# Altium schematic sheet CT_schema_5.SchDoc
size 578 x 363 mm
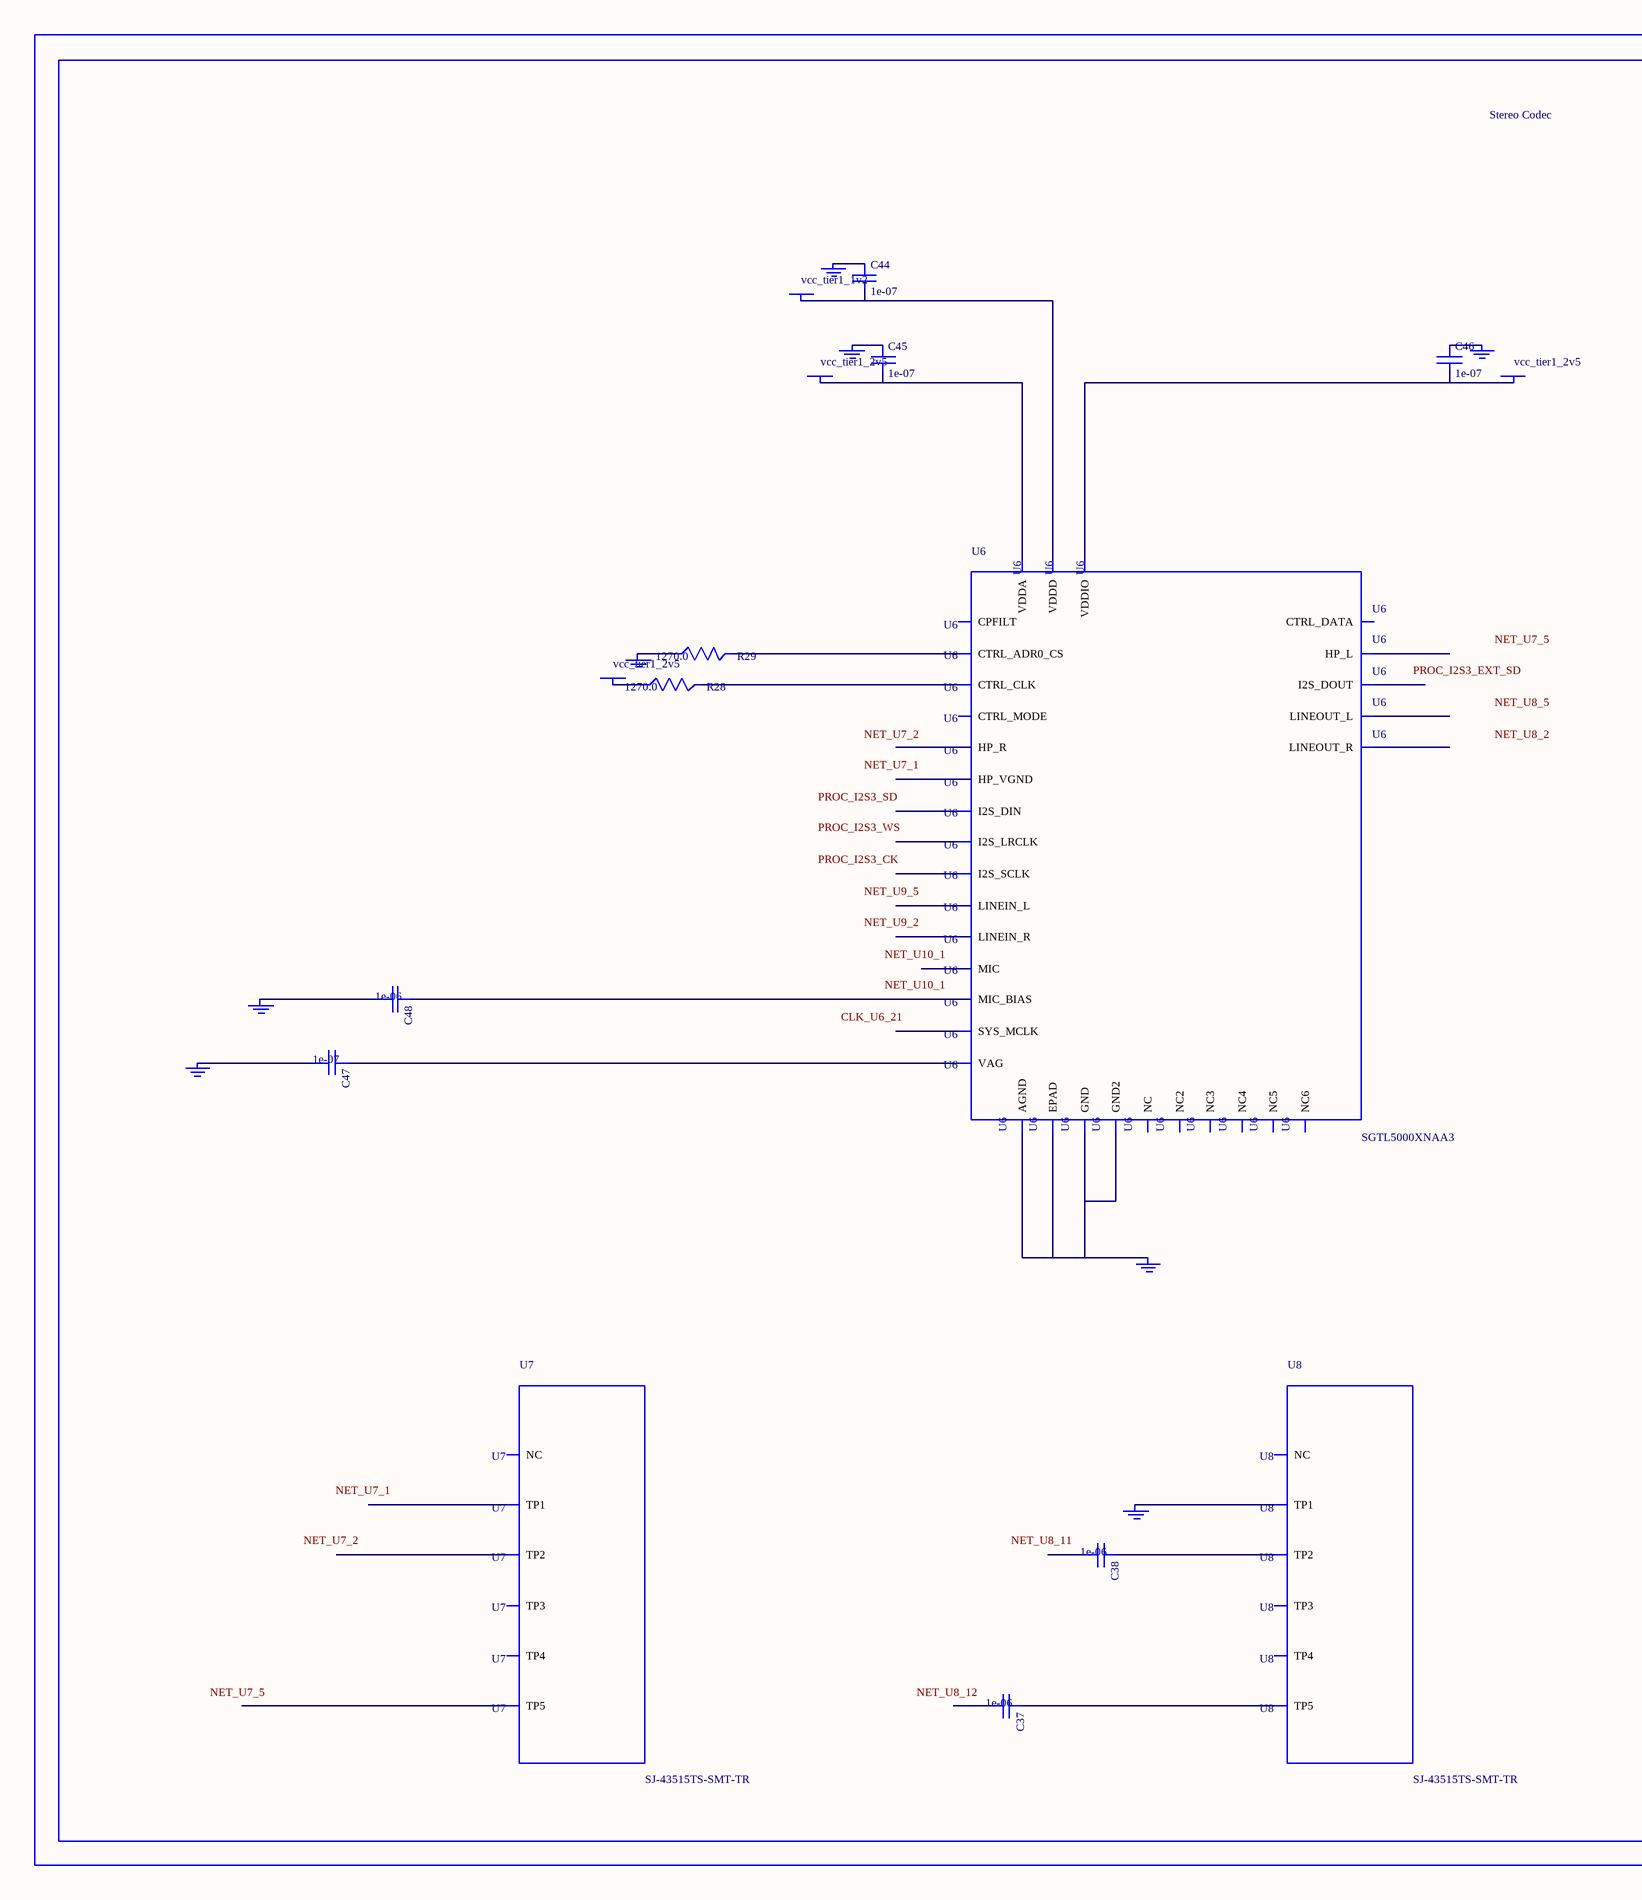
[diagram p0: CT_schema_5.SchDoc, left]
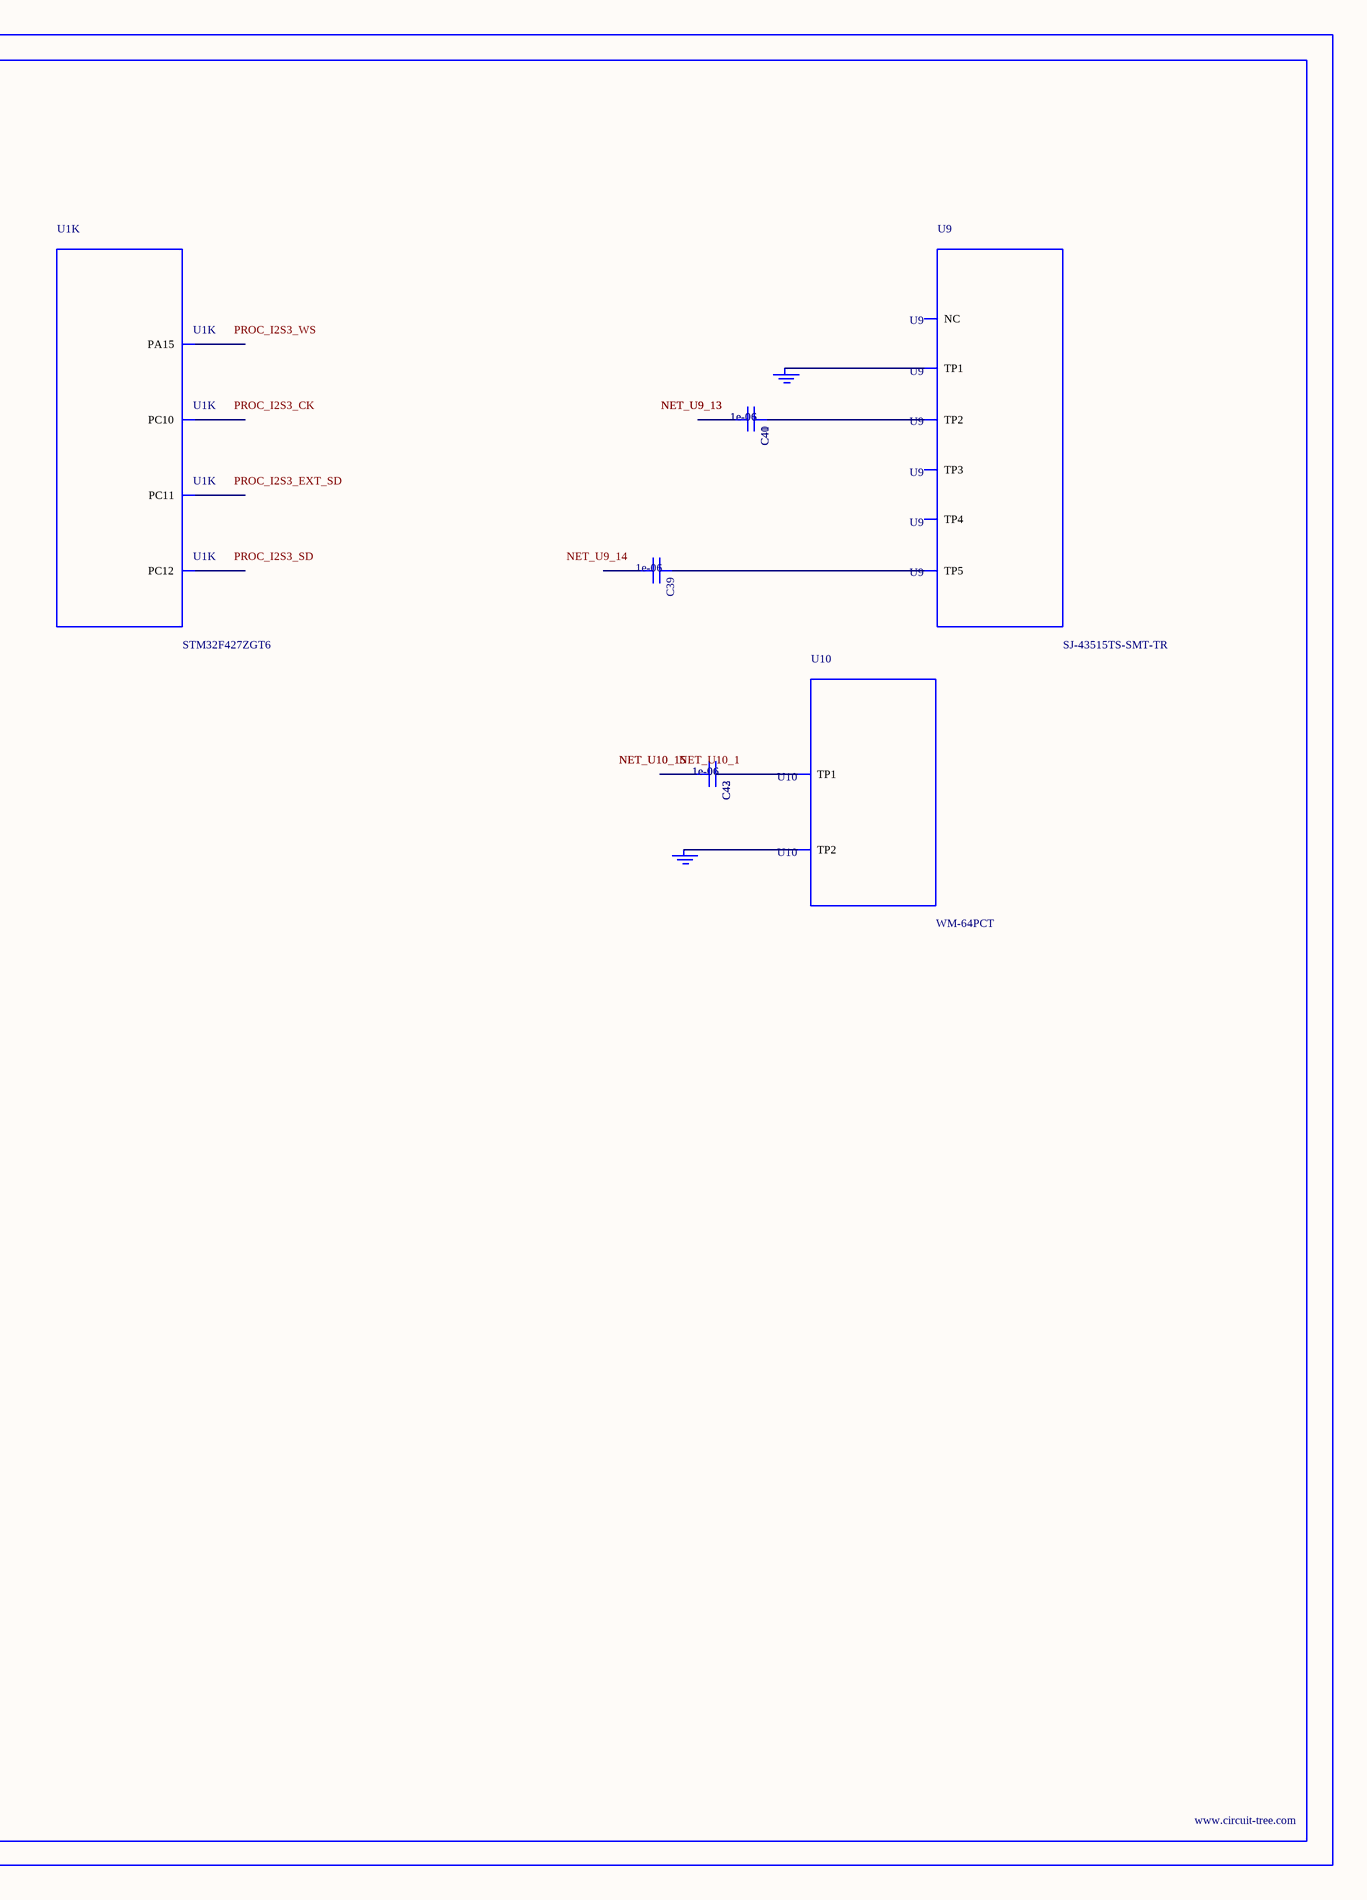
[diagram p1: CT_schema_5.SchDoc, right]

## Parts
BORDER4  (no value)
C37  1e-06  [C0603]
C38  1e-06  [C0603]
C39  1e-06  [C0603]
C40  1e-06  [C0603]
C41  1e-06  [C0603]
C42  1e-06  [C0603]
C43  1e-06  [C0603]
C44  1e-07  [C0402]
C45  1e-07  [C0402]
C46  1e-07  [C0402]
C47  1e-07  [C0402]
C48  1e-06  [C0603]
GND_INSTANCE_4_0  (no value)
GND_INSTANCE_4_1  (no value)
GND_INSTANCE_4_2  (no value)
GND_INSTANCE_4_3  (no value)
GND_INSTANCE_4_4  (no value)
GND_INSTANCE_4_5  (no value)
GND_INSTANCE_4_6  (no value)
GND_INSTANCE_4_7  (no value)
GND_INSTANCE_4_8  (no value)
GND_INSTANCE_4_9  (no value)
GND_INSTANCE_4_10  (no value)
POWER_INSTANCE_4_0  vcc_tier1_2v5
POWER_INSTANCE_4_1  vcc_tier1_2v5
POWER_INSTANCE_4_2  vcc_tier1_2v5
POWER_INSTANCE_4_3  vcc_tier1_1v2
R28  1270.0  [R0603]
R29  1270.0  [R0603]
U1  STM32F427ZGT6  [LQFP144]  (part K of 12)
U6  SGTL5000XNAA3  [QFN-32]
U7  SJ-43515TS-SMT-TR  [SJ-43515TS-SMT-TR]
U8  SJ-43515TS-SMT-TR  [SJ-43515TS-SMT-TR]
U9  SJ-43515TS-SMT-TR  [SJ-43515TS-SMT-TR]
U10  WM-64PCT  [WM-64PC]

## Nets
NetC37_1: C37.1 U8.5(TP5)
NetC38_1: C38.1 U8.2(TP2)
NetC39_1: C39.1 U9.5(TP5)
NetC40_1: C40.1 C41.1 U9.2(TP2)
NetC40_2: C40.2 C41.2
NetC42_1: C42.1 C43.1 U10.1(TP1)
NetC42_2: C42.2 C43.2
NetC44_1: C44.1 GND_INSTANCE_4_5.0(GND)
NetC44_2: C44.2 POWER_INSTANCE_4_3.0(PWR) U6.30(VDDD)
NetC45_1: C45.1 GND_INSTANCE_4_1.0(GND)
NetC45_2: C45.2 POWER_INSTANCE_4_0.0(PWR) U6.5(VDDA)
NetC46_1: C46.1 GND_INSTANCE_4_4.0(GND)
NetC46_2: C46.2 POWER_INSTANCE_4_1.0(PWR) U6.20(VDDIO)
NetC47_1: C47.1 U6.10(VAG)
NetC47_2: C47.2 GND_INSTANCE_4_2.0(GND)
NetC48_1: C48.1 U6.16(MIC_BIAS)
NetC48_2: C48.2 GND_INSTANCE_4_3.0(GND)
NetGND_INSTANCE_4_0_0: GND_INSTANCE_4_0.0(GND) U6.1(GND) U6.3(GND2) U6.7(AGND) U6.EXP(EPAD)
NetGND_INSTANCE_4_6_0: GND_INSTANCE_4_6.0(GND) R29.1
NetGND_INSTANCE_4_7_0: GND_INSTANCE_4_7.0(GND) U8.1(TP1)
NetGND_INSTANCE_4_8_0: GND_INSTANCE_4_8.0(GND) GND_INSTANCE_4_9.0(GND) U9.1(TP1)
NetGND_INSTANCE_4_10_0: GND_INSTANCE_4_10.0(GND) U10.2(TP2)
NetPOWER_INSTANCE_4_2_0: POWER_INSTANCE_4_2.0(PWR) R28.1
NetR28_2: R28.2 U6.29(CTRL_CLK)
NetR29_2: R29.2 U6.31(CTRL_ADR0_CS)

Not connected (* = marked no-connect by the designer): C37 2; C38 2; C39 2; U1 110(PA15) 111(PC10) 112(PC11) 113(PC12); U6 2(HP_R) 4(HP_VGND) 6(HP_L) 8(NC) 9(NC2) 11(LINEOUT_R) 12(LINEOUT_L) 13(LINEIN_R) 14(LINEIN_L) 15(MIC) 17(NC3) 18(CPFILT) 19(NC4) 21(SYS_MCLK) 22(NC5) 23(I2S_LRCLK) 24(I2S_SCLK) 25(I2S_DOUT) 26(I2S_DIN) 27(CTRL_DATA) 28(NC6) 32(CTRL_MODE); U7 1(TP1) 2(TP2) 3(TP3) 4(TP4) 5(TP5) 6(NC); U8 3(TP3) 4(TP4) 6(NC); U9 3(TP3) 4(TP4) 6(NC)

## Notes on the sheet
- Labels drawn without touching a wire or pin: CLK_U6_21, NET_U7_1, NET_U7_2, NET_U7_5, NET_U8_2, NET_U8_5, NET_U8_11, NET_U8_12, NET_U9_2, NET_U9_5, NET_U9_14, NET_U10_1, PROC_I2S3_CK, PROC_I2S3_EXT_SD, PROC_I2S3_SD, PROC_I2S3_WS

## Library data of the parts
BORDER4 = BORDER_PAGE4
C37-C43 C48 = C0603C105K3RACTU
C44-C47 = C0402C104K3RACTU
GND_INSTANCE_4_0-GND_INSTANCE_4_10 = GND
POWER_INSTANCE_4_0-POWER_INSTANCE_4_3 = PWR
R28 R29 = RC0603FR-071K27L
